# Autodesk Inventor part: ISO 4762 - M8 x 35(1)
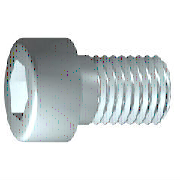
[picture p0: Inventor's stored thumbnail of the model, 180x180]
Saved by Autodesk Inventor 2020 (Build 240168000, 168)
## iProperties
Created: 2019-01
Part Number: ISO 4762 - M8 x 35(1)
Material: Nerezová ocel 440C
Description: Šroub s válcovou hlavou s vnitřním šestihranem
Document SubType Name: Modeling
Standard: ISO 4762
Designer: doma
Standard Revision: Fourth edition 2004-03-01
Standards Organization: ISO
Language: cs-CZ
Size Designation: M8 x 35
Categories: <MemberInstance><Categories><Category DisplayName="Spojovací materiál" InternalName="e4da775c-781d-43d5-af7c-5136215cf5a6" Mnemonic="FSTN"><Category DisplayName
Density: 7.75 g/cm^3
Appearance: Pololeštěná
IsCustomPart: 0
Author: doma
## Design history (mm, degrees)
sketch "Náčrt1"
  geometry: L1 (-2, 0)-(35, 0); L2 (35, 0)-(35, 4); L3 (35, 4)-(3.125, 4); L4 (3.125, 4)-(2.358, 4); L5 (2.358, 4)-(0, 4); L6 (0, 4)-(0, 6.5); L7 (0, 6.5)-(-8, 6.5); L8 (-8, 6.5)-(-8, 3.464); L9 (-8, 3.464)-(-4, 3.464); L10 (-4, 3.464)-(-2, 0); L11 (-16.6, 0)-(43.6, 0) reference; L12 (0, -1.3)-(0, 7.8) reference; L13 (3.125, 4)-(0, 4)
  constraints: 22 end point, 6 parallel, 2 collinear, 2 perpendicular, 1 horizontal, 1 point on line
  dimensions: "d1" = 31.875 distance from line of L3.end L2 (= GEL); "d2" = 0.76691 distance of L4.end L3.end (computed from GAL); "d3" = 8 distance between parallel lines of L8 L6 (= KOH); "d4" = 4 distance of L8.end L9.end (= INTI); "d5" = 60 deg angle of L10 L1; "d6" = 8 diameter of L3 L1 (= GD); "d7" = 8 diameter of L5 L1 (= BDM); "d8" = 6.9282 diameter of L9 L1 (= 1.1547 x SW); "d9" = 13 diameter of L7 L1 (= KOD); "d26" = 35 distance between parallel lines of L12 L2 (= NLG)
revolve "Těleso" sketch "Náčrt1" stored, may be unused: angle "d10" = 90 deg
sketch "Náčrt2"
  geometry: L1 (0, -9.1)-(0, 9.1) reference; L2 (-9.1, 0)-(9.1, 0) reference; L3 (3.464, 0)-(1.732, -3); L4 (1.732, -3)-(-1.732, -3); L5 (-1.732, -3)-(-3.464, 0); L6 (-3.464, 0)-(-1.732, 3); L7 (-1.732, 3)-(1.732, 3); L8 (1.732, 3)-(3.464, 0); 2 further points
  constraints: 12 end point, 1 coincident, 1 horizontal alignment, 1 point on line, 12 other
extrude "Drážka" join sketch "Náčrt2" stored distance "d11" = 10; taper "d12" = 0 deg
workplane "Work Plane1"
fillet "Fillet2" dims "d30" = 0.1 (= R)
body "Solid1"
fillet "Zaoblení1" dims "d17" = 0.8 (= RR)
feature "Závit" dims "d13" = 31.875 (= GEL), "d14" = 0
chamfer "Zkosení1" distance "d15" = 0.76681 (= -0.5 x SPD + 0.5 x GD); stored, may be unused: second distance "d16" = 0.76681 (= GUL), angle "d27" = 45 deg
other parameters: "GD" = 8 [user parameter; used in 2 equation terms], "NLG" = 35 [user parameter; used in 1 equation term], "GEL" = 31.875 [user parameter; used in 2 equation terms], "KOD" = 13 [user parameter; used in 1 equation term], "KOH" = 8 [user parameter; used in 1 equation term], "INTI" = 4 [user parameter; used in 1 equation term], "GAL" = 0.76681 (= 0.61345 x PTC) [user parameter; used in 1 equation term], "GUL" = 0.76681 (= 0.61345 x PTC) [user parameter; used in 1 equation term], "BDM" = 8 (= NND) [user parameter; used in 1 equation term], "SW" = 6 [user parameter; used in 2 equation terms], "RR" = 0.8 [user parameter; used in 1 equation term], "SPD" = 6.46637 (= NND - 1.2269 x PTC) [user parameter; used in 1 equation term], "d19" = 0, "d28" = 0, "d29" = 0, "R" = 0.1 [user parameter; used in 1 equation term], "TOA" = 30 deg [user parameter], "GD1" = 6.46637 (= THREADDIA - 1.2269 x PTC) [user parameter], "THREADDIA" = 8 [user parameter; used in 1 equation term], "FAWI" = 45 deg [user parameter], "TPU" = 8 (computed from PTC) [user parameter], "PTC" = 1.25 [user parameter; used in 5 equation terms], "NND" = 8 [user parameter; used in 2 equation terms], "E0" = 6.93 (= 1.155 x SW) [user parameter]
